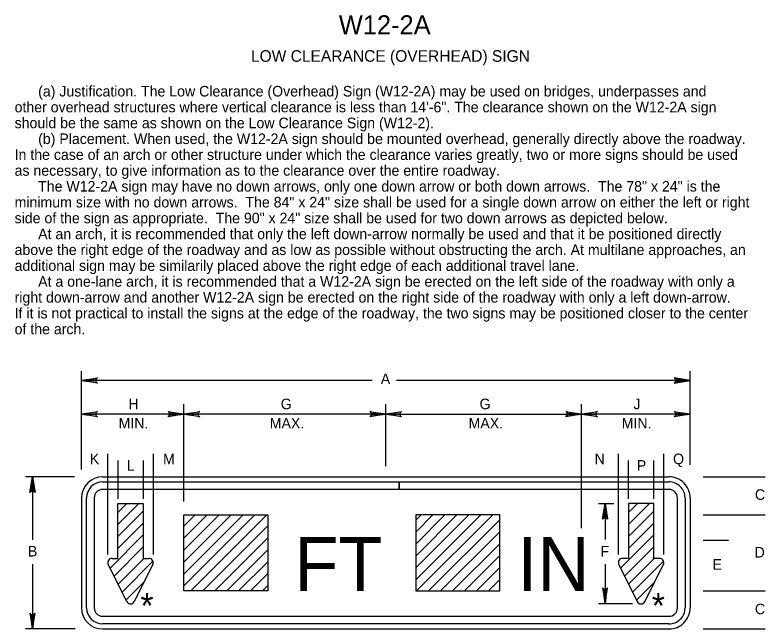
# Model space of a CAD drawing. Extents: x 0.013 to 0.2, y 0.004 to 0.259.
# Drawn here: x 0.0226 to 0.2001, y 0.1138 to 0.2591 of the extents above; entities that cross this region are included whole.
import ezdxf

# ---------------------------------------------------------------- set-up
doc = ezdxf.new("R2010")
doc.units = 0
for name, color, linetype in [('1', 7, 'Continuous'), ('2', 7, 'Continuous'), ('3', 7, 'Continuous')]:
    doc.layers.add(name, color=color, linetype=linetype)

# ---------------------------------------------------------------- blocks, each defined once
blk = doc.blocks.new('RARROW')
at = {"layer": '3'}
for p, q in [((-2.156, 0.28500000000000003), (-2.2665, 0.384625)), ((-2.2665, 0.384625), (0, 0)), ((0, 0), (-2.2665, -0.379125)), ((-2.156, 0.28500000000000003), (-2.075625, 0.12075)), ((0, 0), (-2.156, 0.28500000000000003)), ((-2.14975, -0.2705), (0, 0)), ((-2.075625, 0.12075), (0, 0)), ((0, 0), (-2.074, -0.108)), ((-2.2665, -0.379125), (-2.14975, -0.2705)), ((-2.074, -0.108), (-2.14975, -0.2705))]:
    blk.add_line(p, q, dxfattribs=at)

msp = doc.modelspace()

# ---------------------------------------------------------------- linework, layer by layer
at = {"layer": '1'}
for p, q in [((0.04456421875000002, 0.13146806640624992), (0.04456421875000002, 0.1552611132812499)), ((0.055344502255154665, 0.13146806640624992), (0.055344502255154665, 0.1552611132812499)), ((0.1653693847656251, 0.13146806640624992), (0.1653693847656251, 0.1552611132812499)), ((0.17613704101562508, 0.13146806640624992), (0.17613704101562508, 0.1552611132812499)), ((0.04694523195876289, 0.1537011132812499), (0.04694523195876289, 0.1446092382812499)), ((0.05294523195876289, 0.1537254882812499), (0.05294523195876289, 0.14465798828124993)), ((0.16775275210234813, 0.14465798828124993), (0.16775275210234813, 0.1537254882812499)), ((0.17375275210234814, 0.14465798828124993), (0.17375275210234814, 0.1537254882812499)), ((0.026746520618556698, 0.14983937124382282), (0.026746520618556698, 0.13491902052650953)), ((0.04334899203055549, 0.14863937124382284), (0.1135362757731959, 0.14863937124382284)), ((0.1135362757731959, 0.14863937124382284), (0.1135362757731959, 0.14683937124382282)), ((0.1135362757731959, 0.14683937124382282), (0.1135362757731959, 0.14863937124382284)), ((0.1135362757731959, 0.14863937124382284), (0.17734899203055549, 0.14863937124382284)), ((0.1135362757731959, 0.14683937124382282), (0.04334899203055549, 0.14683937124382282)), ((0.1773489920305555, 0.14683937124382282), (0.1135362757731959, 0.14683937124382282)), ((0.038348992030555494, 0.14483937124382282), (0.038348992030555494, 0.11883937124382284)), ((0.039548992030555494, 0.11883937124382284), (0.039548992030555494, 0.14483937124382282)), ((0.0413489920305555, 0.14483937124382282), (0.0413489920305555, 0.11883937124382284)), ((0.1793489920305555, 0.11883937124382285), (0.17934899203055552, 0.14483937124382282)), ((0.1811489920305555, 0.14483937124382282), (0.18114899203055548, 0.11883937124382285)), ((0.1823489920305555, 0.1448393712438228), (0.1823489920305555, 0.11883937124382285)), ((0.04694523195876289, 0.1435482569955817), (0.05294523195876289, 0.1435482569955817)), ((0.04694523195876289, 0.1305482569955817), (0.04694523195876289, 0.1435482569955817)), ((0.04694523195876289, 0.14139425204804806), (0.04909923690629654, 0.1435482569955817)), ((0.0469452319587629, 0.13856582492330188), (0.051927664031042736, 0.1435482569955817)), ((0.05294523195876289, 0.1435482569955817), (0.0529452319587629, 0.1305482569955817)), ((0.16222109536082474, 0.14353328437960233), (0.16222109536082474, 0.1350388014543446)), ((0.17375275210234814, 0.1435482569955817), (0.16775275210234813, 0.1435482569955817)), ((0.16775275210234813, 0.1435482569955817), (0.16775275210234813, 0.1305482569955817)), ((0.16775275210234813, 0.14139425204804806), (0.16990675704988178, 0.1435482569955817)), ((0.16775275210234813, 0.13856582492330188), (0.172735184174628, 0.1435482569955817)), ((0.17375275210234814, 0.1305482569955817), (0.17375275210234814, 0.1435482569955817)), ((0.04694523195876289, 0.1357373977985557), (0.05294523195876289, 0.14173739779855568)), ((0.06256101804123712, 0.1381555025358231), (0.06524488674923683, 0.14083937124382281)), ((0.06256101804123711, 0.1353270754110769), (0.06807331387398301, 0.14083937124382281)), ((0.06256101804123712, 0.13249864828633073), (0.07090174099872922, 0.14083937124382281)), ((0.06256101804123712, 0.12967022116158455), (0.07373016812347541, 0.14083937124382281)), ((0.06256101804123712, 0.12684179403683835), (0.07655859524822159, 0.14083937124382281)), ((0.06256101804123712, 0.12401336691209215), (0.07938702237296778, 0.14083937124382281)), ((0.06421544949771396, 0.12283937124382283), (0.08221544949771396, 0.14083937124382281)), ((0.1174206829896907, 0.13958488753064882), (0.1186751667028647, 0.14083937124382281)), ((0.1174206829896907, 0.13675646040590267), (0.12150359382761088, 0.14083937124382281)), ((0.1174206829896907, 0.13392803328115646), (0.12433202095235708, 0.14083937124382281)), ((0.11742068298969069, 0.13109960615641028), (0.12716044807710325, 0.14083937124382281)), ((0.1174206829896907, 0.12827117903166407), (0.12998887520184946, 0.14083937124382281)), ((0.11742068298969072, 0.12544275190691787), (0.13281730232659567, 0.14083937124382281)), ((0.11764572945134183, 0.12283937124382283), (0.13564572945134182, 0.14083937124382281)), ((0.16775275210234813, 0.1357373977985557), (0.17375275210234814, 0.14173739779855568)), ((0.046945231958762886, 0.13290897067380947), (0.05294523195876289, 0.13890897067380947)), ((0.12047415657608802, 0.12283937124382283), (0.13730431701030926, 0.13966953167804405)), ((0.16775275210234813, 0.13290897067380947), (0.17375275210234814, 0.13890897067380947)), ((0.06704387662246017, 0.12283937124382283), (0.08244465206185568, 0.13824014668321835)), ((0.12330258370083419, 0.12283937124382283), (0.13730431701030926, 0.1368411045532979)), ((0.04510113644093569, 0.1282364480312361), (0.0529452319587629, 0.13608054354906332)), ((0.06987230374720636, 0.12283937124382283), (0.08244465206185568, 0.13541171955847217)), ((0.16590865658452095, 0.1282364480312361), (0.17375275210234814, 0.13608054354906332)), ((0.04604394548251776, 0.12635082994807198), (0.0529452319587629, 0.1332521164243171)), ((0.1261310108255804, 0.12283937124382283), (0.13730431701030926, 0.1340126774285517)), ((0.166851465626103, 0.12635082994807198), (0.17375275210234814, 0.1332521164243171)), ((0.07270073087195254, 0.12283937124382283), (0.08244465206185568, 0.13258329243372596)), ((0.04556326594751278, 0.1305482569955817), (0.04694523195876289, 0.1305482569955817)), ((0.046986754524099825, 0.12446521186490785), (0.05306979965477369, 0.1305482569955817)), ((0.04792956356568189, 0.12257959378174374), (0.05525961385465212, 0.12990964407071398)), ((0.05294523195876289, 0.1305482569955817), (0.05432719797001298, 0.1305482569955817)), ((0.07552915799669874, 0.12283937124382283), (0.08244465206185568, 0.12975486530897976)), ((0.12895943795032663, 0.12283937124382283), (0.13730431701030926, 0.13118425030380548)), ((0.16775275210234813, 0.1305482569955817), (0.16637078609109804, 0.1305482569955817)), ((0.16779427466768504, 0.12446521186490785), (0.17387731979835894, 0.1305482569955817)), ((0.16873708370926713, 0.12257959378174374), (0.17606713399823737, 0.12990964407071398)), ((0.17513471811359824, 0.1305482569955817), (0.17375275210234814, 0.1305482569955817)), ((0.026746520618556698, 0.12916953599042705), (0.026746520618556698, 0.11383937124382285)), ((0.04905080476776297, 0.12033711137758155), (0.04466883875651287, 0.12910104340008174)), ((0.055221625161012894, 0.12910104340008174), (0.0508396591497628, 0.12033711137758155)), ((0.13178786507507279, 0.12283937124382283), (0.13730431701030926, 0.1283558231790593)), ((0.16222109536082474, 0.12916953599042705), (0.16222109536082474, 0.11985656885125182)), ((0.16547635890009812, 0.12910104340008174), (0.1698583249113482, 0.12033711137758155)), ((0.17164717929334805, 0.12033711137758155), (0.17602914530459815, 0.12910104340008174)), ((0.07835758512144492, 0.12283937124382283), (0.08244465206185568, 0.12692643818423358)), ((0.04885275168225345, 0.1206743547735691), (0.05316381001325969, 0.12498541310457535)), ((0.134616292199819, 0.12283937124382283), (0.13730431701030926, 0.1255273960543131)), ((0.1696602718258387, 0.1206743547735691), (0.17397133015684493, 0.12498541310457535)), ((0.08118601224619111, 0.12283937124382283), (0.0824446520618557, 0.1240980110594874)), ((0.04334899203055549, 0.11683937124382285), (0.17734899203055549, 0.11683937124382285)), ((0.17734899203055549, 0.11503937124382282), (0.04334899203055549, 0.11503937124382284))]:
    msp.add_line(p, q, dxfattribs=at)
for points in [[(0.08244465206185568, 0.12283937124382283), (0.06256101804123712, 0.12283937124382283), (0.06256101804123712, 0.14083937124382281), (0.08244465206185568, 0.14083937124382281)], [(0.1174206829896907, 0.12283937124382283), (0.13730431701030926, 0.12283937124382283), (0.13730431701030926, 0.14083937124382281), (0.1174206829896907, 0.14083937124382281)]]:
    msp.add_lwpolyline(points, close=True, dxfattribs=at)
for centre, radius, start, end in [((0.04334899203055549, 0.14483937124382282), 0.005, 90, 180), ((0.1773489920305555, 0.14483937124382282), 0.005, 1.5631940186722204e-13, 90.00000000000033), ((0.04334899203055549, 0.14483937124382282), 0.0037999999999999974, 90, 180), ((0.1773489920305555, 0.14483937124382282), 0.0038000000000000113, 0, 90.00000000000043), ((0.04334899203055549, 0.14483937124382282), 0.002, 90, 180), ((0.1773489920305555, 0.14483937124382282), 0.002, 0, 90), ((0.04556326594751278, 0.1295482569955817), 0.001, 90.00000000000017, 206.56505117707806), ((0.05432719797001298, 0.1295482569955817), 0.001, 333.434948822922, 90), ((0.16637078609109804, 0.1295482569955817), 0.001, 90.00000000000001, 206.565051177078), ((0.17513471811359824, 0.1295482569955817), 0.0009999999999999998, 333.4349488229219, 89.99999999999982), ((0.04994523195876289, 0.1207843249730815), 0.001, 206.56505117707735, 333.4349488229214), ((0.17075275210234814, 0.1207843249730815), 0.001, 206.56505117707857, 333.43494882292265), ((0.04334899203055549, 0.11883937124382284), 0.005, 180, 270), ((0.04334899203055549, 0.11883937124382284), 0.0037999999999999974, 180, 270), ((0.04334899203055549, 0.11883937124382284), 0.002, 180, 270), ((0.17734899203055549, 0.11883937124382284), 0.005, 270, 2.2737367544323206e-13), ((0.17734899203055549, 0.11883937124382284), 0.002, 270, 3.979039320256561e-13), ((0.17734899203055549, 0.11883937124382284), 0.0038000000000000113, 270, 2.2737367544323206e-13)]:
    msp.add_arc(centre, radius, start, end, dxfattribs=at)
at = {"layer": '3'}
for p, q in [((0.03834899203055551, 0.15156296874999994), (0.03834899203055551, 0.1747845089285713)), ((0.18234899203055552, 0.15266946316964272), (0.18234899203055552, 0.1747845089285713)), ((0.10710704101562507, 0.17264473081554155), (0.03834899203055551, 0.17264473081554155)), ((0.1823489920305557, 0.17264473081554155), (0.11285954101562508, 0.17264473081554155)), ((0.06256101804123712, 0.14400519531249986), (0.06256101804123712, 0.16701654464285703)), ((0.1103489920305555, 0.15232090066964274), (0.1103489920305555, 0.16701654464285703)), ((0.15665822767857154, 0.13768127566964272), (0.15665822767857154, 0.16701654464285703)), ((0.06256101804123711, 0.16466997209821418), (0.03834899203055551, 0.16466997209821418)), ((0.1103489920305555, 0.16466997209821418), (0.0625610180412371, 0.16466997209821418)), ((0.11034899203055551, 0.1646699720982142), (0.15665822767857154, 0.1646699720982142)), ((0.18234899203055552, 0.1646699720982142), (0.15665822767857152, 0.1646699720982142)), ((0.036691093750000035, 0.14983937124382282), (0.025069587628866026, 0.14983937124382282)), ((0.04334899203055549, 0.14983937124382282), (0.17734899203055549, 0.14983937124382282)), ((0.1854562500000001, 0.14983937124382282), (0.20006952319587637, 0.14983937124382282)), ((0.1606639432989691, 0.14353328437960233), (0.16429079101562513, 0.14353328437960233)), ((0.1854562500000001, 0.14083937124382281), (0.20006952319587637, 0.14083937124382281)), ((0.19144529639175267, 0.13476929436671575), (0.1854562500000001, 0.13476929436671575)), ((0.1854562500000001, 0.12283937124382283), (0.20006952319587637, 0.12283937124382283)), ((0.1606639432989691, 0.11985656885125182), (0.16874874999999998, 0.11985656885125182)), ((0.036861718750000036, 0.11383937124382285), (0.025069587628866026, 0.11383937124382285)), ((0.04334899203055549, 0.11383937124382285), (0.17734899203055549, 0.11383937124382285)), ((0.1854562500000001, 0.11383937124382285), (0.20006952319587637, 0.11383937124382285))]:
    msp.add_line(p, q, dxfattribs=at)

# ---------------------------------------------------------------- block references
at = {"layer": '3', "xscale": 0.0016545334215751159}
for p, yscale, rotation in [((0.03834899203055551, 0.17264473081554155), 0.0016366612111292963, 180), ((0.03834899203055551, 0.16466997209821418), 0.0016366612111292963, 180), ((0.0625610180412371, 0.16466997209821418), 0.0016366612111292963, 180), ((0.1103489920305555, 0.1646699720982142), 0.0016366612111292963, 180), ((0.15665822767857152, 0.1646699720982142), 0.0016366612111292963, 180), ((0.026746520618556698, 0.14983937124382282), 0.0016366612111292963, 89.99999999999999), ((0.16222109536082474, 0.14353328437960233), 0.0016366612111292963, 89.99999999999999), ((0.16222109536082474, 0.11985656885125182), -0.0016366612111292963, -89.99999999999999), ((0.026746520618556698, 0.11383937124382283), -0.0016366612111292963, -89.99999999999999)]:
    msp.add_blockref('RARROW', p, dxfattribs=dict(at, yscale=yscale, rotation=rotation))
for p, yscale in [((0.18234899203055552, 0.17264473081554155), -0.0016366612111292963), ((0.0625610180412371, 0.16466997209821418), 0.0016366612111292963), ((0.1103489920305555, 0.1646699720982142), 0.0016366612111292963), ((0.15665822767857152, 0.1646699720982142), 0.0016366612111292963), ((0.18234899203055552, 0.1646699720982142), 0.0016366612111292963)]:
    msp.add_blockref('RARROW', p, dxfattribs=dict(at, yscale=yscale))

# ---------------------------------------------------------------- texts
at = {"layer": '1'}
for s, height, p in [('W12-2A', 0.0045000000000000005, (0.09922227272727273, 0.2545)), ('LOW CLEARANCE (OVERHEAD) SIGN', 0.00275025, (0.0784403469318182, 0.248))]:
    msp.add_text(s, height=height, dxfattribs=at).set_placement(p)
at = {"layer": '2'}
for s, p in [('      (a) Justification. The Low Clearance (Overhead) Sign (W12-2A) may be used on bridges, underpasses and', (0.02251589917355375, 0.23979256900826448)), ('other overhead structures where vertical clearance is less than 14\'-6". The clearance shown on the W12-2A sign ', (0.02251589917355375, 0.2360428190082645)), ('should be the same as shown on the Low Clearance Sign (W12-2).', (0.02251589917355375, 0.2322930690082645)), ('      (b) Placement. When used, the W12-2A sign should be mounted overhead, generally directly above the roadway.', (0.02251589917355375, 0.2285433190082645)), ('In the case of an arch or other structure under which the clearance varies greatly, two or more signs should be used', (0.02251589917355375, 0.2247935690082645)), ('as necessary, to give information as to the clearance over the entire roadway.', (0.02251589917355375, 0.22104381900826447)), ('      The W12-2A sign may have no down arrows, only one down arrow or both down arrows.  The 78" x 24" is the ', (0.02251589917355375, 0.2172940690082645)), ('minimum size with no down arrows.  The 84" x 24" size shall be used for a single down arrow on either the left or right', (0.02251589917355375, 0.2135443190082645)), ('side of the sign as appropriate.  The 90" x 24" size shall be used for two down arrows as depicted below.', (0.02251589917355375, 0.2097945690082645)), ('      At an arch, it is recommended that only the left down-arrow normally be used and that it be positioned directly', (0.02251589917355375, 0.2060448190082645)), ('above the right edge of the roadway and as low as possible without obstructing the arch. At multilane approaches, an', (0.02251589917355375, 0.2022950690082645)), ('additional sign may be similarily placed above the right edge of each additional travel lane.', (0.02251589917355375, 0.1985453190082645)), ('      At a one-lane arch, it is recommended that a W12-2A sign be erected on the left side of the roadway with only a ', (0.02251589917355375, 0.1947955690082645)), ('right down-arrow and another W12-2A sign be erected on the right side of the roadway with only a left down-arrow.', (0.02251589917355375, 0.19104581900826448)), ('If it is not practical to install the signs at the edge of the roadway, the two signs may be positioned closer to the center', (0.02251589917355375, 0.1872960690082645)), ('of the arch.', (0.02251589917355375, 0.1835463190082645))]:
    msp.add_text(s, height=0.0024997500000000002, dxfattribs=at).set_placement(p)
at = {"layer": '3'}
for s, height, p in [('A', 0.0024997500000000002, (0.10916521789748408, 0.17175686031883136)), ('H', 0.0024997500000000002, (0.049443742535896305, 0.16582268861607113)), ('G', 0.0024997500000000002, (0.08548729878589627, 0.16582268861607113)), ('G', 0.0024997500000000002, (0.13253590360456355, 0.16582268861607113)), ('J', 0.0024997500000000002, (0.16894002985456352, 0.16582268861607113)), ('MIN.', 0.0024997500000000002, (0.047122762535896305, 0.16126647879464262)), ('MAX.', 0.0024997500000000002, (0.08287809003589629, 0.16126647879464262)), ('MAX.', 0.0024997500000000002, (0.12992669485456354, 0.16126647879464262)), ('MIN.', 0.0024997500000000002, (0.1661713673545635, 0.16126647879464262)), ('K', 0.0024997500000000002, (0.040305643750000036, 0.1528206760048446)), ('M', 0.0024997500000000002, (0.05763596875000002, 0.1528206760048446)), ('N', 0.0024997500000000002, (0.15974515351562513, 0.1528206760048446)), ('Q', 0.0024997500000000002, (0.1783122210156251, 0.1528206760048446)), ('L', 0.0024997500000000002, (0.04904191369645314, 0.1512850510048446)), ('P', 0.0024997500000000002, (0.16972949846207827, 0.1512850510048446)), ('FT', 0.012748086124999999, (0.08871760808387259, 0.12284120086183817)), ('IN', 0.012748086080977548, (0.1414936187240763, 0.12284120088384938)), ('B', 0.0024997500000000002, (0.025662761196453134, 0.13098436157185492)), ('F', 0.0024997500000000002, (0.1611361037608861, 0.13098436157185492)), ('D', 0.0024997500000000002, (0.1976208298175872, 0.1307447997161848)), ('*', 0.005938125, (0.05230656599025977, 0.11639400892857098)), ('*', 0.005938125, (0.1732826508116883, 0.11639400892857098))]:
    msp.add_text(s, height=height, dxfattribs=at).set_placement(p)
for s, p in [('C', (0.19769241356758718, 0.14437925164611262)), ('E', (0.18767865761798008, 0.12787005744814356)), ('C', (0.19769241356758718, 0.11732933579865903))]:
    msp.add_text(s, height=0.0024997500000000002, rotation=360, dxfattribs=at).set_placement(p)

doc.saveas('drawing.dxf')
